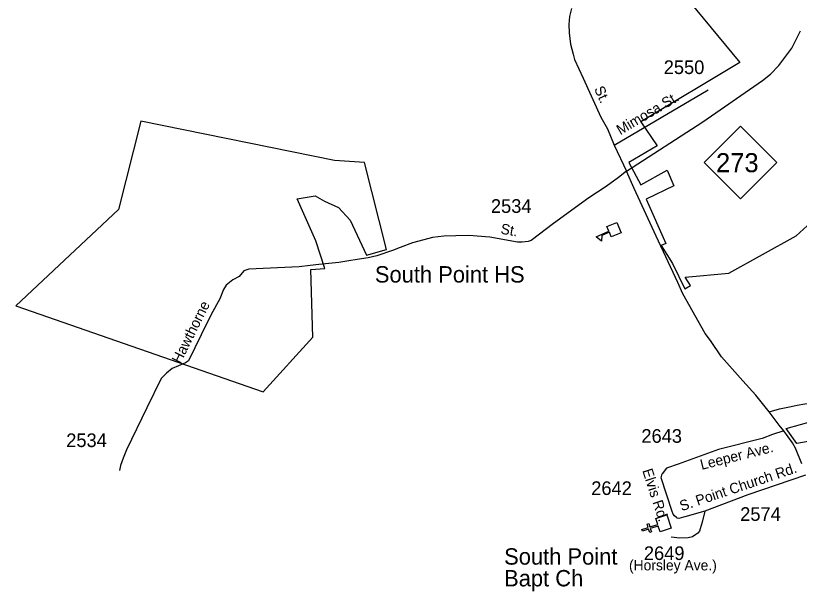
# Model space of a CAD drawing. Extents: x 1364363 to 1407445, y 538563 to 573342.
# Drawn here: x 1385792 to 1392969, y 539061 to 544334 of the extents above; entities that cross this region are included whole.
import ezdxf

# ---------------------------------------------------------------- set-up
doc = ezdxf.new("R2010")
doc.units = 0
for name, color, linetype in [('Exist Boundary Political City Limit New', 7, 'Continuous'), ('Exist Boundary Political City Limit New Hole', 7, 'Continuous'), ('Exist Cultural Church CELL', 7, 'Continuous'), ('Exist Cultural Church Label', 7, 'Continuous'), ('Exist Cultural Educational Facility High CELL', 7, 'Continuous'), ('Exist Cultural Educational Facility High Label', 7, 'Continuous'), ('Exist Road Primary NC Attributed', 7, 'Continuous'), ('Exist Road Primary NC Shield CELL', 7, 'Continuous'), ('Exist Road Primary NC Shield Number Label', 7, 'Continuous'), ('Exist Road Secondary Type 51 Attributed', 7, 'Continuous'), ('Exist Road Secondary Type 51 Label', 7, 'Continuous'), ('Exist Road Secondary Type 51 Number Label', 7, 'Continuous')]:
    doc.layers.add(name, color=color, linetype=linetype)

msp = doc.modelspace()

# ---------------------------------------------------------------- linework, layer by layer
at = {"layer": 'Exist Boundary Political City Limit New'}
msp.add_lwpolyline([(1397442.4, 541163.5), (1397393.9, 541022.2), (1397227, 541083.8), (1397072.1, 541140.9), (1392946.8, 540414.4), (1392848.4, 540552.2), (1393503.5, 540734.4), (1394081.5, 540895.2), (1397738.2, 541926.1), (1397751.5, 541765.6), (1397734, 541550.9), (1397709.5, 541446.2), (1397531.5, 541275.2), (1397442.4, 541163.5)], dxfattribs=at)
at = {"layer": 'Exist Boundary Political City Limit New Hole'}
for points in [[(1393033.4, 546283.3), (1392264.2, 545962.6), (1392518.5, 545579.9), (1392704, 545295.1), (1391827.5, 544630.4), (1392423.4, 543905.9), (1391518, 543360.8), (1391666.9, 543142.4), (1391407.8, 542989.1), (1391517.1, 542785.8), (1391759.5, 542918.8), (1391820.9, 542775.8), (1391565.2, 542652.9), (1391747.9, 542247.4), (1391704.2, 542228.9), (1391808.1, 542063.2), (1391919.6, 541832.3), (1391973.5, 541863.9), (1391923.1, 541938.4), (1392323.5, 541974.4), (1392939.9, 542316.6), (1393175.9, 542530.1)], [(1388624, 542018.1), (1388541, 542270.6), (1388371.6, 542656.2), (1388534.4, 542682.8), (1388620.6, 542636.2), (1388750.1, 542576.4), (1388856.4, 542460.1), (1389005.8, 542141), (1389188.4, 542190.9), (1388985.8, 542988.6), (1388711.9, 543008.5), (1386939.1, 543367.4), (1386733.4, 542559.8), (1385792.2, 541676.1), (1388059.6, 540888.1), (1388512.4, 541388.1), (1388496.5, 542010.5), (1388624, 542018.1)]]:
    msp.add_lwpolyline(points, dxfattribs=at)
at = {"layer": 'Exist Cultural Church CELL'}
msp.add_lwpolyline([(1391694.8, 539605.5), (1391676.9, 539659.5), (1391604.6, 539635.7), (1391614.6, 539605.3), (1391599.4, 539600.3), (1391589.4, 539630.7), (1391532.3, 539611.9), (1391527.2, 539627.1), (1391584.4, 539645.9), (1391574.4, 539676.3), (1391589.5, 539681.3), (1391599.5, 539650.9), (1391671.9, 539674.7), (1391654, 539729.5), (1391755.1, 539762.8), (1391795.9, 539638.7)], close=True, dxfattribs=at)
at = {"layer": 'Exist Cultural Educational Facility High CELL'}
msp.add_lwpolyline([(1391337.3, 542346.2), (1391247.1, 542308.1), (1391229.2, 542350.5), (1391160, 542321.4), (1391156, 542268.6), (1391107.1, 542309.4), (1391225.5, 542359.4), (1391207.6, 542401.8), (1391297.8, 542439.8)], close=True, dxfattribs=at)
at = {"layer": 'Exist Road Primary NC Attributed'}
for points in [[(1391387.2, 542909.7), (1392084.7, 543360.9), (1392630.8, 543739.7), (1392706, 543798.2), (1392781.8, 543878.7), (1392899.1, 544036.2), (1392978.5, 544194.7)], [(1392693, 540706.4), (1392572, 540859.4), (1392450.6, 540989.6), (1392257.7, 541210.3), (1392155.8, 541359.8), (1392106.1, 541421.6), (1391903.7, 541787.2), (1391855.9, 541890.7), (1391659.2, 542313.5), (1391455.2, 542750.4), (1391387.2, 542909.7)], [(1392827.9, 540532.1), (1392784.9, 540583), (1392693, 540706.4)], [(1392991.7, 540228.7), (1392934.8, 540373.9), (1392905.8, 540422.5), (1392827.9, 540532.1)]]:
    msp.add_lwpolyline(points, dxfattribs=at)
at = {"layer": 'Exist Road Primary NC Shield CELL'}
msp.add_lwpolyline([(1392097, 542989.7), (1392430, 543322.7), (1392763, 542989.7), (1392430, 542656.7)], close=True, dxfattribs=at)
at = {"layer": 'Exist Road Secondary Type 51 Attributed'}
for q in [(1392134.2, 543656), (1391387.2, 542909.7)]:
    msp.add_line((1391274.6, 543148.6), q, dxfattribs=at)
for points in [[(1390881.7, 544399.3), (1390864.5, 544326.1), (1390858.9, 544251.9), (1390862.3, 544177.6), (1390873.4, 544072.2), (1390897, 543981.4), (1390911.1, 543931.4), (1390988.5, 543763), (1391152.6, 543403.4), (1391211.3, 543296.5), (1391274.6, 543148.6)], [(1391387.2, 542909.7), (1391314.5, 542852.8), (1391199.6, 542768.6), (1391042.4, 542666.2), (1390718.8, 542429.6), (1390512.8, 542275.1), (1390486.1, 542266.2), (1390429.7, 542260.2), (1390388.1, 542260.2), (1390133.6, 542304.4), (1389941.3, 542320.3), (1389824, 542318.1), (1389715, 542313.5), (1389611.1, 542303.6), (1389530.9, 542280.6), (1389427.8, 542252.6), (1389312.9, 542211.8), (1389244.8, 542183.8), (1389099, 542134.5), (1389021.8, 542116.7), (1388920.8, 542101.8), (1388843.5, 542089.9), (1388787.4, 542079.4), (1388769.3, 542076.2), (1388750.8, 542072.9), (1388567.2, 542054.6), (1388489.6, 542044.9), (1388388.7, 542034.2), (1387927.4, 542013), (1387880.9, 541997.1), (1387839.8, 541943.9), (1387782.1, 541915.3), (1387719.9, 541865.9), (1387696.3, 541825.1), (1387661.9, 541741.3), (1387582.5, 541597.4), (1387490.2, 541410.5), (1387376.4, 541171.6), (1387348.5, 541154.4), (1387284.1, 541127.1), (1387224, 541101.3), (1387172.4, 541060.5), (1387125.2, 541009.2), (1386992.1, 540742.6), (1386807.5, 540357.4), (1386775.3, 540282.2), (1386751.7, 540213.5), (1386742.4, 540168.9)], [(1392693, 540706.4), (1392788.7, 540731.6), (1392878.2, 540751.5), (1392949.3, 540766.1), (1393020.4, 540779.3), (1393099.7, 540791.3), (1393172.1, 540801.9), (1393245.9, 540804.5), (1393304.7, 540812.5), (1393355.3, 540825.8), (1393416.1, 540861.6), (1393466.6, 540904), (1393526.8, 540954.4), (1393585.6, 541006.1), (1393639.5, 541041.9), (1393706.5, 541077.7), (1393742, 541092.3), (1393783.1, 541098.9), (1393854.1, 541108.2), (1393937.5, 541112.2), (1394045.5, 541121.5), (1394145.2, 541126.8), (1394249.1, 541141.4), (1394297, 541158.6)], [(1392827.9, 540532.1), (1392722.4, 540498.2), (1392629.5, 540461.1), (1392227.7, 540360.3), (1391858.6, 540225), (1391754.1, 540187.9), (1391711.7, 540137.5)], [(1391842.9, 539736), (1391826.3, 539753.4), (1391814.8, 539767.8), (1391803.2, 539791), (1391703.5, 540100.3), (1391711.7, 540137.5)], [(1393025.9, 540124.2), (1392497.6, 539946.5), (1392102.3, 539794.9)], [(1392102.3, 539794.9), (1392079.4, 539694.5), (1392071.2, 539664), (1392060.2, 539634.9), (1392054.8, 539611), (1392041.1, 539595.1), (1392022, 539580.5), (1391991.9, 539560.6), (1391950.9, 539550), (1391874.3, 539548.7), (1391796.4, 539556.6)], [(1392102.3, 539794.9), (1391919.2, 539742.6), (1391908.1, 539740.3), (1391864.6, 539729), (1391853, 539730.6), (1391847.6, 539732.1), (1391842.9, 539736)]]:
    msp.add_lwpolyline(points, dxfattribs=at)

# ---------------------------------------------------------------- texts
at = {"layer": 'Exist Cultural Church Label'}
for s, p in [('South Point ', (1390265.6, 539305.6)), ('Bapt Ch', (1390265.6, 539106.4))]:
    msp.add_text(s, height=150, dxfattribs=at).set_placement(p)
at = {"layer": 'Exist Cultural Educational Facility High Label'}
msp.add_text('South Point HS', height=150, dxfattribs=at).set_placement((1389082.1, 541889.6))
at = {"layer": 'Exist Road Primary NC Shield Number Label'}
msp.add_text('273', height=175, dxfattribs=at).set_placement((1392206.1, 542900))
at = {"layer": 'Exist Road Secondary Type 51 Label'}
for s, rotation, p in [('St.', 294.54334, (1391087.8, 543663.9)), ('Mimosa St.', 30.55484, (1391329.6, 543238.2)), ('St.', 350.15117, (1390228.6, 542337.9)), ('Hawthorne', 63.71423, (1387301.7, 541140)), ('Leeper Ave.', 14.08032, (1392074.3, 540173.1)), ('S. Point Church Rd.', 18.59291, (1391891.4, 539794.5)), ('Elvis Rd.', 287.86401, (1391530.1, 540168.1))]:
    msp.add_text(s, height=95, rotation=rotation, dxfattribs=at).set_placement(p)
msp.add_text('(Horsley Ave.)', height=95, dxfattribs=at).set_placement((1391409, 539252.9))
at = {"layer": 'Exist Road Secondary Type 51 Number Label'}
for s, p in [('2550', (1391727.4, 543799.3)), ('2534', (1390144.7, 542527.9)), ('2534', (1386255.1, 540382.5)), ('2643', (1391522.7, 540421.7)), ('2642', (1391063.4, 539943.6)), ('2574', (1392427.7, 539706.6)), ('2649', (1391545.5, 539348))]:
    msp.add_text(s, height=125, dxfattribs=at).set_placement(p)

doc.saveas('drawing.dxf')
